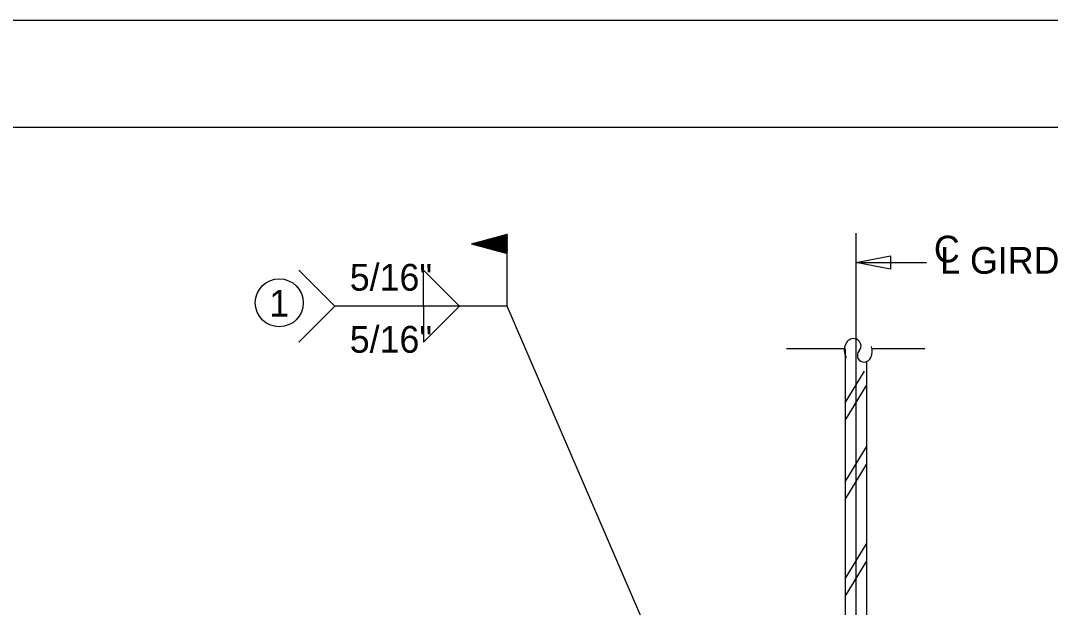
# Model space of a CAD drawing. Extents: x -125.5 to -89.4, y -5.1 to 16.9.
# Drawn here: x -120.383 to -115.571, y 14.192 to 16.934 of the extents above; entities that cross this region are included whole.
import ezdxf

# ---------------------------------------------------------------- set-up
doc = ezdxf.new("R2010")
doc.units = 0
for name, color, linetype in [('BR_AUTO DIMENSION', 7, 'Continuous'), ('BR_BORDER LINES', 7, 'Continuous'), ('BR_CENTER LINES', 7, 'Continuous'), ('BR_STRUCTURAL STEEL', 7, 'Continuous'), ('BR_TEXT', 7, 'Continuous'), ('Level 31', 7, 'Continuous')]:
    doc.layers.add(name, color=color, linetype=linetype)

msp = doc.modelspace()

# ---------------------------------------------------------------- linework, layer by layer
at = {"layer": 'BR_AUTO DIMENSION'}
for p, q in [((-118.2772, 15.8902), (-118.1091, 15.9353)), ((-118.1089, 15.9024), (-118.1349, 15.9284)), ((-118.1089, 15.9055), (-118.1324, 15.929)), ((-118.1089, 15.9087), (-118.1299, 15.9297)), ((-118.1089, 15.9119), (-118.1274, 15.9304)), ((-118.1089, 15.915), (-118.1249, 15.931)), ((-118.1089, 15.9182), (-118.1224, 15.9317)), ((-118.1089, 15.9214), (-118.1199, 15.9324)), ((-118.1089, 15.9246), (-118.1174, 15.933)), ((-118.1089, 15.9277), (-118.1149, 15.9337)), ((-118.1089, 15.9309), (-118.1124, 15.9344)), ((-118.1089, 15.9341), (-118.1099, 15.9351)), ((-118.1091, 15.5991), (-118.1091, 15.9353)), ((-118.2772, 15.8902), (-118.1091, 15.8452)), ((-118.2732, 15.8892), (-118.2749, 15.8909)), ((-118.2689, 15.888), (-118.2724, 15.8915)), ((-118.2646, 15.8869), (-118.2699, 15.8922)), ((-118.2602, 15.8857), (-118.2674, 15.8929)), ((-118.2559, 15.8845), (-118.2649, 15.8935)), ((-118.2516, 15.8834), (-118.2624, 15.8942)), ((-118.2472, 15.8822), (-118.2599, 15.8949)), ((-118.2429, 15.8811), (-118.2574, 15.8955)), ((-118.2386, 15.8799), (-118.2549, 15.8962)), ((-118.2343, 15.8787), (-118.2524, 15.8969)), ((-118.2299, 15.8776), (-118.2499, 15.8975)), ((-118.2256, 15.8764), (-118.2474, 15.8982)), ((-118.2213, 15.8753), (-118.2449, 15.8989)), ((-118.217, 15.8741), (-118.2424, 15.8996)), ((-118.2126, 15.8729), (-118.2399, 15.9002)), ((-118.2083, 15.8718), (-118.2374, 15.9009)), ((-118.204, 15.8706), (-118.2349, 15.9016)), ((-118.1996, 15.8695), (-118.2324, 15.9022)), ((-118.1953, 15.8683), (-118.2299, 15.9029)), ((-118.191, 15.8671), (-118.2274, 15.9036)), ((-118.1866, 15.866), (-118.2249, 15.9042)), ((-118.1823, 15.8648), (-118.2224, 15.9049)), ((-118.178, 15.8637), (-118.2199, 15.9056)), ((-118.1737, 15.8625), (-118.2174, 15.9063)), ((-118.1693, 15.8613), (-118.2149, 15.9069)), ((-118.165, 15.8602), (-118.2124, 15.9076)), ((-118.1607, 15.859), (-118.2099, 15.9083)), ((-118.1563, 15.8579), (-118.2074, 15.9089)), ((-118.152, 15.8567), (-118.2049, 15.9096)), ((-118.1477, 15.8555), (-118.2024, 15.9103)), ((-118.1433, 15.8544), (-118.1999, 15.9109)), ((-118.139, 15.8532), (-118.1974, 15.9116)), ((-118.1347, 15.8521), (-118.1949, 15.9123)), ((-118.1304, 15.8509), (-118.1924, 15.913)), ((-118.126, 15.8497), (-118.1899, 15.9136)), ((-118.1217, 15.8486), (-118.1874, 15.9143)), ((-118.1174, 15.8474), (-118.1849, 15.915)), ((-118.113, 15.8463), (-118.1824, 15.9156)), ((-118.1091, 15.8455), (-118.1799, 15.9163)), ((-118.1089, 15.8485), (-118.1774, 15.917)), ((-118.1089, 15.8517), (-118.1749, 15.9176)), ((-118.1089, 15.8548), (-118.1724, 15.9183)), ((-118.1089, 15.858), (-118.1699, 15.919)), ((-118.1089, 15.8612), (-118.1674, 15.9197)), ((-118.1089, 15.8643), (-118.1649, 15.9203)), ((-118.1089, 15.8675), (-118.1624, 15.921)), ((-118.1089, 15.8707), (-118.1599, 15.9217)), ((-118.1089, 15.8739), (-118.1574, 15.9223)), ((-118.1089, 15.877), (-118.1549, 15.923)), ((-118.1089, 15.8802), (-118.1524, 15.9237)), ((-118.1089, 15.8834), (-118.1499, 15.9243)), ((-118.1089, 15.8865), (-118.1474, 15.925)), ((-118.1089, 15.8897), (-118.1449, 15.9257)), ((-118.1089, 15.8929), (-118.1424, 15.9263)), ((-118.1089, 15.896), (-118.1399, 15.927)), ((-118.1089, 15.8992), (-118.1374, 15.9277)), ((-116.4811, 15.8038), (-116.1506, 15.8038)), ((-119.0832, 15.7672), (-118.9151, 15.5991)), ((-118.5013, 15.5991), (-118.5013, 15.7672)), ((-118.3332, 15.5991), (-118.5013, 15.7672)), ((-118.9151, 15.5991), (-119.0832, 15.431)), ((-118.1091, 15.5991), (-118.9151, 15.5991)), ((-118.3332, 15.5991), (-118.5013, 15.431)), ((-118.5013, 15.5991), (-118.5013, 15.431)), ((-117.1478, 13.3682), (-118.1091, 15.5991))]:
    msp.add_line(p, q, dxfattribs=at)
msp.add_lwpolyline([(-116.3186, 15.7725), (-116.4811, 15.8038), (-116.3186, 15.835)], close=True, dxfattribs=at)
msp.add_circle((-119.1748, 15.6153), 0.1121, dxfattribs=at)
at = {"layer": 'BR_BORDER LINES'}
msp.add_line((-90.0334, 16.4338), (-123.6994, 16.4338), dxfattribs=at)
at = {"layer": 'BR_CENTER LINES'}
msp.add_line((-116.4811, 15.9412), (-116.4811, 12.8489), dxfattribs=at)
at = {"layer": 'BR_STRUCTURAL STEEL'}
for p, q in [((-116.5311, 15.4006), (-116.5311, 13.4682)), ((-116.4311, 15.3403), (-116.4311, 13.4682)), ((-116.5311, 15.1479), (-116.4406, 15.2955)), ((-116.5311, 15.0651), (-116.4311, 15.2282)), ((-116.5311, 14.7786), (-116.4311, 14.9416)), ((-116.5311, 14.6958), (-116.4311, 14.8589)), ((-116.5311, 14.3256), (-116.4311, 14.4887)), ((-116.5311, 14.2428), (-116.4311, 14.4059))]:
    msp.add_line(p, q, dxfattribs=at)
at = {"layer": 'BR_TEXT'}
for p, q in [((-116.8038, 15.4016), (-116.534, 15.4016)), ((-116.4049, 15.4016), (-116.1587, 15.4016))]:
    msp.add_line(p, q, dxfattribs=at)
for centre, radius, start, end in [((-116.491, 15.4071), 0.0406, 83.2422, 155.6187), ((-116.4902, 15.4137), 0.034, 316.8236, 83.2422), ((-116.4626, 15.3943), 0.0718, 155.6187, 208.3414), ((-116.475, 15.389), 0.0713, 335.6333, 17.6449), ((-116.4428, 15.3692), 0.031, 136.8236, 275.5224), ((-116.4434, 15.3747), 0.0365, 275.5224, 335.6333)]:
    msp.add_arc(centre, radius, start, end, dxfattribs=at)
at = {"layer": 'Level 31'}
msp.add_line((-89.5328, 16.9339), (-125.5328, 16.9339), dxfattribs=at)

# ---------------------------------------------------------------- texts
at = {"layer": 'BR_AUTO DIMENSION'}
msp.add_text('1', height=0.125, dxfattribs=at).set_placement((-119.2216, 15.5503))
at = {"layer": 'BR_TEXT'}
for s, p in [('C', (-116.1158, 15.8037)), ('L GIRDER', (-116.0864, 15.7511)), ('5/16"', (-118.8454, 15.672)), ('5/16"', (-118.8454, 15.382))]:
    msp.add_text(s, height=0.125, dxfattribs=at).set_placement(p)

doc.saveas('drawing.dxf')
